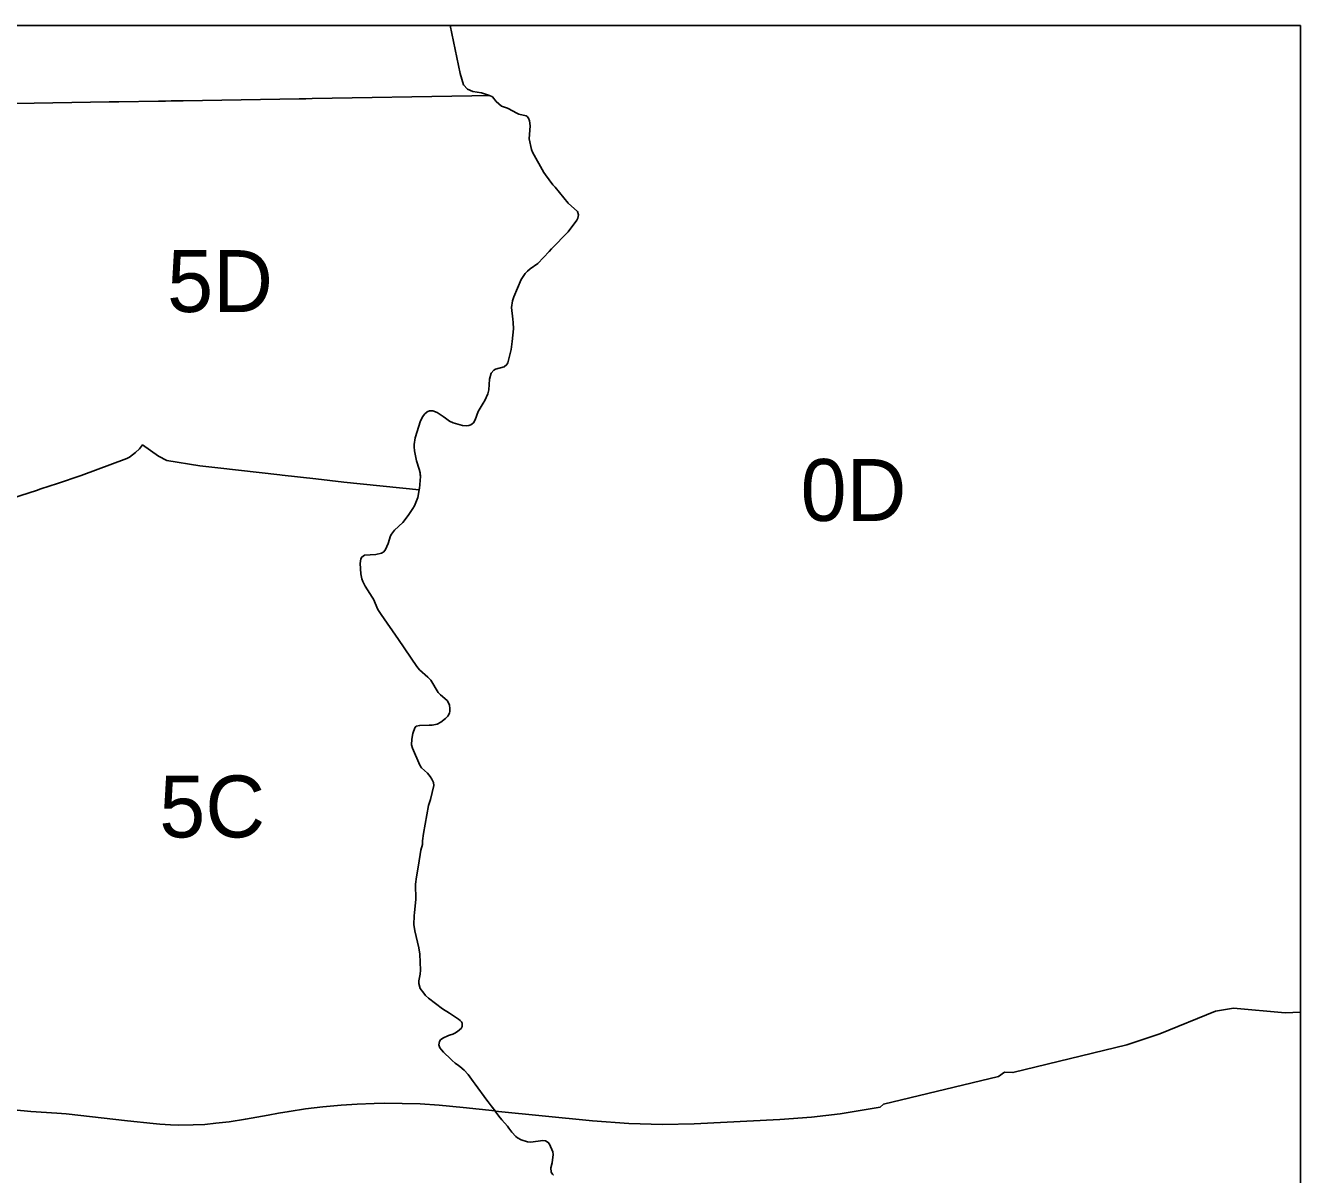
# Model space of a CAD drawing. Extents: x 152750 to 166250, y 378996 to 390000.
# Drawn here: x 162130 to 166250, y 386288 to 390000 of the extents above; entities that cross this region are included whole.
import ezdxf

# ---------------------------------------------------------------- set-up
doc = ezdxf.new("R2010")
doc.units = 0
doc.layers.add('BLT_Nummers', color=7, linetype='Continuous')
doc.layers.add('BLT_Shapes', color=7, linetype='Continuous')

msp = doc.modelspace()

# ---------------------------------------------------------------- linework, layer by layer
at = {"layer": 'BLT_Shapes'}
for p, q in [((163502.8, 390000), (157101, 390000)), ((162560.7, 389755.6), (162432.5, 389753.4)), ((163630.1, 389773.7), (163572.1, 389772.7)), ((163688, 389732.8), (163668.9, 389739.1)), ((163758.8, 389692.2), (163755.7, 389700.3)), ((163760.9, 389675.5), (163758.8, 389692.2)), ((163805.4, 389525.1), (163768.7, 389591.2)), ((163810.2, 389518), (163805.4, 389525.1)), ((163834.3, 389485.3), (163810.2, 389518)), ((163703.9, 389110.2), (163708.2, 389123.6)), ((163699.2, 388953), (163702.2, 388970.4)), ((163702.2, 388970.4), (163703.4, 388978.6)), ((163648.9, 388889.7), (163676.7, 388896.8)), ((163676.7, 388896.8), (163686, 388905)), ((163630, 388857.9), (163634.7, 388876.8)), ((163407.2, 388723.2), (163414.2, 388737.1)), ((163569.1, 388709.5), (163577.5, 388716.4)), ((162959.7, 388547.7), (163068.9, 388535.3)), ((163068.9, 388535.3), (163158.8, 388525.2)), ((163158.8, 388525.2), (163402.6, 388500)), ((163382.4, 388439.1), (163387.6, 388448.2)), ((163313, 388356.8), (163322.6, 388370)), ((163211.8, 388261.6), (163214, 388277.5)), ((163214, 388277.5), (163217.6, 388282.9)), ((163217.6, 388282.9), (163226.2, 388288.7)), ((163213.9, 388228.5), (163211.8, 388261.6)), ((163217.3, 388211.9), (163213.9, 388228.5)), ((163220.4, 388203.3), (163217.3, 388211.9)), ((163227.7, 388189.1), (163220.4, 388203.3)), ((163250.4, 388152.9), (163227.7, 388189.1)), ((163335.1, 388016.5), (163279.1, 388096.7)), ((163394.4, 387928.9), (163335.1, 388016.5)), ((163439.6, 387884.9), (163430.8, 387895.1)), ((163500, 387778.2), (163501.6, 387784.4)), ((163393.1, 387735.9), (163404.2, 387738.7)), ((163404.2, 387738.7), (163434.8, 387739.8)), ((163434.8, 387739.8), (163444, 387739.9)), ((163472.9, 387748.8), (163487.9, 387760.9)), ((163449.1, 387554.8), (163443.5, 387565.7)), ((163416.7, 387389.7), (163432.3, 387479.7)), ((163408.3, 387335.3), (163413.1, 387353.8)), ((163388.2, 387074.9), (163385.4, 387095.5)), ((163401.1, 386913.8), (163405.3, 386934.9)), ((163417.1, 386873.3), (163406.1, 386889.1)), ((163538.7, 386761.1), (163539.3, 386761.9)), ((163534.1, 386637.2), (163529.4, 386640.6)), ((163547.8, 386625.2), (163534.1, 386637.2)), ((162025.7, 386503.7), (162147.9, 386491.8)), ((162981.9, 386491.8), (163035, 386499.8)), ((163256.9, 386517.4), (163289.8, 386518.2)), ((163406.1, 386515.9), (163466.7, 386512)), ((163625.5, 386522.3), (163620.9, 386527.8)), ((163635.4, 386510.3), (163625.5, 386522.3)), ((163647.5, 386493.2), (163635.4, 386510.3)), ((162261.4, 386483.8), (162460.5, 386461.3)), ((163648.2, 386492.3), (163647.5, 386493.2)), ((163659.3, 386476.6), (163648.2, 386492.3)), ((162598.6, 386448.3), (162624.5, 386447.9)), ((163692.3, 386437.9), (163688, 386443.6)), ((163702.1, 386424.9), (163692.3, 386437.9)), ((163714.7, 386411.1), (163702.1, 386424.9)), ((163752.3, 386393.7), (163732.2, 386400.4)), ((163834, 386361.3), (163823.4, 386385.6)), ((163833.1, 386289.3), (163829.1, 386296))]:
    msp.add_line(p, q, dxfattribs=at)
msp.add_lwpolyline([(163502.8, 390000), (163535.2, 389844.9), (163545.6, 389808), (163558.4, 389794.1), (163576.3, 389787), (163604.3, 389782.4), (163630.1, 389773.7), (163638.8, 389769.4), (163651.4, 389754.9), (163668.9, 389739.1), (163688, 389732.8), (163689.6, 389731.7), (163717.5, 389716.4), (163724, 389713.8), (163747.9, 389707.8), (163751.8, 389705.6), (163755.7, 389700.3), (163758.8, 389692.2), (163760.9, 389675.5), (163757.3, 389633.6), (163765.5, 389599), (163768.7, 389591.2), (163805.4, 389525.1), (163810.2, 389518), (163834.3, 389485.3), (163841.5, 389477.3), (163883.6, 389426), (163913.9, 389399.4), (163917.3, 389388.8), (163915, 389378), (163911.5, 389370.7), (163883.5, 389333.4), (163829.9, 389278.5), (163822.6, 389270.4), (163785.9, 389230.9), (163760.8, 389213.4), (163752.4, 389206.6), (163745, 389198.4), (163732.4, 389179), (163708.2, 389123.6), (163703.9, 389110.2), (163701, 389089.4), (163705.4, 389051.7), (163706.6, 389041), (163707, 389019.8), (163703.4, 388978.6), (163702.2, 388970.4), (163699.2, 388953), (163688.7, 388910.6), (163686, 388905), (163676.7, 388896.8), (163648.9, 388889.7), (163643.1, 388886.6), (163634.7, 388876.8), (163630, 388857.9), (163627.2, 388822.8), (163623.8, 388809.6), (163614.1, 388788.1), (163608.8, 388779.8), (163592.5, 388752.8), (163583, 388726.5), (163577.5, 388716.4), (163569.1, 388709.5), (163563.2, 388707.4), (163555.3, 388706.7), (163542.5, 388707.6), (163511.8, 388716.3), (163500, 388722.1), (163487.6, 388731.3), (163480.1, 388736.7), (163460.5, 388750.1), (163446.4, 388755.2), (163436, 388755.5), (163428.7, 388752), (163419.5, 388744.1), (163414.2, 388737.1), (163407.2, 388723.2), (163389.8, 388667.4), (163386.5, 388646.8), (163386.3, 388638.9), (163387.4, 388626.4), (163393.7, 388593.7), (163402.5, 388566.9), (163405.2, 388555), (163406.2, 388542.9), (163403.1, 388503.9), (163402.9, 388502.2), (163402.6, 388500), (163398.3, 388474.8), (163387.6, 388448.2), (163382.4, 388439.1), (163367, 388416.5), (163349.2, 388394.6), (163322.6, 388370), (163313, 388356.8), (163310.1, 388351.5), (163302.5, 388326.8), (163293.8, 388307.3), (163288.2, 388300.1), (163280.9, 388295.5), (163262.9, 388291.2), (163226.2, 388288.7), (163217.6, 388282.9), (163214, 388277.5), (163211.8, 388261.6), (163213.9, 388228.5), (163217.3, 388211.9), (163220.4, 388203.3), (163227.7, 388189.1), (163250.4, 388152.9), (163254.3, 388146.5), (163268.4, 388113.7), (163279.1, 388096.7), (163335.1, 388016.5), (163394.4, 387928.9), (163403.5, 387918.7), (163430.8, 387895.1), (163439.6, 387884.9), (163463.3, 387845.6), (163470.8, 387837.1), (163492.7, 387819.2), (163497.6, 387811.5), (163500, 387804.4), (163502, 387793.6), (163501.6, 387784.4), (163500, 387778.2), (163495.4, 387769), (163487.9, 387760.9), (163472.9, 387748.8), (163461, 387742.9), (163444, 387739.9), (163434.8, 387739.8), (163404.2, 387738.7), (163393.1, 387735.9), (163388.8, 387731.2), (163381.7, 387713.1), (163378.2, 387694.1), (163377.7, 387676), (163380.4, 387665.3), (163404.1, 387610.4), (163409.9, 387601.9), (163429.1, 387584.3), (163437.4, 387573.6), (163443.5, 387565.7), (163449.1, 387554.8), (163450.1, 387545.1), (163438.5, 387500), (163432.3, 387479.7), (163416.7, 387389.7), (163413.1, 387365.7), (163413.1, 387353.8), (163408.3, 387335.3), (163400.1, 387287.6), (163393.6, 387250), (163390.1, 387225.9), (163391.7, 387176), (163387.6, 387134.3), (163386.6, 387124), (163385.4, 387095.5), (163388.2, 387074.9), (163401.6, 387020.8), (163404.5, 387000), (163406.4, 386947.8), (163405.3, 386934.9), (163401.1, 386913.8), (163401.2, 386905.3), (163406.1, 386889.1), (163417.1, 386873.3), (163423.2, 386866.3), (163432.3, 386857.7), (163477.4, 386823.5), (163500, 386808.9), (163529.1, 386790), (163534.9, 386785.9), (163539.1, 386781.7), (163541.4, 386777), (163541.6, 386766.6), (163539.3, 386761.9), (163538.7, 386761.1), (163526.2, 386750), (163517.7, 386744.5), (163510.8, 386741.6), (163500, 386737.6), (163497.6, 386736.7), (163478.9, 386728.2), (163471.5, 386722.6), (163468.2, 386718), (163466, 386707), (163469.5, 386697.3), (163474.9, 386690.6), (163480.6, 386683.4), (163505.2, 386660.2), (163509.4, 386656.2), (163519.1, 386648), (163529.4, 386640.6), (163534.1, 386637.2), (163547.8, 386625.2), (163560.9, 386611.1), (163577, 386588.9), (163583.5, 386579.7), (163620.9, 386527.8), (163625.5, 386522.3), (163635.4, 386510.3), (163648.2, 386492.3), (163962.9, 386460.9), (164080.2, 386453), (164188.8, 386449.7), (164290.9, 386451.9), (164567.7, 386465.9), (164670.2, 386472.8), (164762.6, 386484), (164891.8, 386505.3), (164902.6, 386515), (165274.7, 386604.9), (165293.8, 386618.2), (165320.9, 386617.1), (165689, 386707.4), (165795.4, 386742.4), (165975.1, 386815.3), (166033.6, 386825), (166200.7, 386810.6), (166250, 386812.5), (166250, 390000)], close=True, dxfattribs=at)
for points in [[(163630.1, 389773.7), (163604.3, 389782.4), (163576.3, 389787), (163558.4, 389794.1), (163545.6, 389808), (163535.2, 389844.9), (163502.8, 390000)], [(161394, 389735.8), (161394.2, 389735.8), (161430.1, 389736.4), (161703, 389741.1), (161734.5, 389741.6), (162400.4, 389752.9), (162432.5, 389753.4), (162560.7, 389755.6), (162582.3, 389755.9), (162600.8, 389756.3), (162639.5, 389756.9), (163014.9, 389763.3), (163035.8, 389763.6), (163057.2, 389764), (163572.1, 389772.7), (163630.1, 389773.7)], [(162432.5, 389753.4), (162400.4, 389752.9), (161734.5, 389741.6)], [(162600.8, 389756.3), (162582.3, 389755.9), (162560.7, 389755.6)], [(163572.1, 389772.7), (163057.2, 389764), (163035.8, 389763.6), (163014.9, 389763.3), (162639.5, 389756.9), (162600.8, 389756.3)], [(163668.9, 389739.1), (163651.4, 389754.9), (163638.8, 389769.4), (163630.1, 389773.7)], [(163755.7, 389700.3), (163751.8, 389705.6), (163747.9, 389707.8), (163724, 389713.8), (163717.5, 389716.4), (163689.6, 389731.7), (163688, 389732.8)], [(163768.7, 389591.2), (163765.5, 389599), (163757.3, 389633.6), (163760.9, 389675.5)], [(163913.9, 389399.4), (163883.6, 389426), (163841.5, 389477.3), (163834.3, 389485.3)], [(163745, 389198.4), (163752.4, 389206.6), (163760.8, 389213.4), (163785.9, 389230.9), (163822.6, 389270.4), (163829.9, 389278.5), (163883.5, 389333.4), (163911.5, 389370.7), (163915, 389378), (163917.3, 389388.8), (163913.9, 389399.4)], [(163708.2, 389123.6), (163732.4, 389179), (163745, 389198.4)], [(163703.4, 388978.6), (163707, 389019.8), (163706.6, 389041), (163705.4, 389051.7), (163701, 389089.4), (163703.9, 389110.2)], [(163686, 388905), (163688.7, 388910.6), (163699.2, 388953)], [(163634.7, 388876.8), (163643.1, 388886.6), (163648.9, 388889.7)], [(163592.5, 388752.8), (163608.8, 388779.8), (163614.1, 388788.1), (163623.8, 388809.6), (163627.2, 388822.8), (163630, 388857.9)], [(163386.5, 388646.8), (163389.8, 388667.4), (163407.2, 388723.2)], [(163414.2, 388737.1), (163419.5, 388744.1), (163428.7, 388752)], [(163428.7, 388752), (163436, 388755.5), (163446.4, 388755.2)], [(163446.4, 388755.2), (163460.5, 388750.1), (163480.1, 388736.7), (163487.6, 388731.3), (163500, 388722.1), (163511.8, 388716.3), (163542.5, 388707.6)], [(163577.5, 388716.4), (163583, 388726.5), (163592.5, 388752.8)], [(163542.5, 388707.6), (163555.3, 388706.7), (163563.2, 388707.4), (163569.1, 388709.5)], [(163402.6, 388500), (163158.8, 388525.2), (163068.9, 388535.3), (162959.7, 388547.7), (162952.6, 388548.5), (162751.9, 388570.9), (162693.6, 388577.4), (162586.8, 388594.8), (162559.9, 388608.6), (162508.9, 388645.2), (162498.3, 388632.5), (162485.7, 388620.4), (162466.4, 388605.7), (162458.1, 388601.4), (162310.5, 388546), (162233.8, 388520.7), (162180.4, 388502.8), (162165.8, 388498), (162088.6, 388472.8)], [(162498.3, 388632.5), (162508.9, 388645.2), (162559.9, 388608.6), (162586.8, 388594.8)], [(163387.4, 388626.4), (163386.3, 388638.9), (163386.5, 388646.8)], [(162180.4, 388502.8), (162233.8, 388520.7), (162310.5, 388546), (162458.1, 388601.4), (162466.4, 388605.7)], [(162466.4, 388605.7), (162485.7, 388620.4), (162498.3, 388632.5)], [(163405.2, 388555), (163402.5, 388566.9), (163393.7, 388593.7), (163387.4, 388626.4)], [(162586.8, 388594.8), (162693.6, 388577.4), (162751.9, 388570.9), (162952.6, 388548.5), (162959.7, 388547.7)], [(163402.6, 388500), (163402.9, 388502.2), (163403.1, 388503.9), (163406.2, 388542.9), (163405.8, 388547.2), (163405.2, 388555)], [(162088.6, 388472.8), (162165.8, 388498), (162180.4, 388502.8)], [(163387.6, 388448.2), (163398.3, 388474.8), (163402.6, 388500)], [(163322.6, 388370), (163349.2, 388394.6), (163367, 388416.5), (163382.4, 388439.1)], [(163293.8, 388307.3), (163302.5, 388326.8), (163310.1, 388351.5), (163313, 388356.8)], [(163226.2, 388288.7), (163262.9, 388291.2), (163280.9, 388295.5), (163288.2, 388300.1), (163293.8, 388307.3)], [(163279.1, 388096.7), (163268.4, 388113.7), (163254.3, 388146.5), (163250.4, 388152.9)], [(163430.8, 387895.1), (163403.5, 387918.7), (163394.4, 387928.9)], [(163501.6, 387784.4), (163502, 387793.6), (163500, 387804.4), (163497.6, 387811.5), (163492.7, 387819.2), (163470.8, 387837.1), (163463.3, 387845.6), (163439.6, 387884.9)], [(163487.9, 387760.9), (163495.4, 387769), (163500, 387778.2)], [(163377.7, 387676), (163378.2, 387694.1), (163381.7, 387713.1), (163388.8, 387731.2), (163393.1, 387735.9)], [(163444, 387739.9), (163461, 387742.9), (163472.9, 387748.8)], [(163404.1, 387610.4), (163380.4, 387665.3), (163377.7, 387676)], [(163443.5, 387565.7), (163437.4, 387573.6), (163429.1, 387584.3), (163409.9, 387601.9), (163404.1, 387610.4)], [(163432.3, 387479.7), (163438.5, 387500), (163450.1, 387545.1), (163449.1, 387554.8)], [(163413.1, 387353.8), (163413.1, 387365.7), (163416.7, 387389.7)], [(163390.1, 387225.9), (163393.6, 387250), (163400.1, 387287.6), (163408.3, 387335.3)], [(163385.4, 387095.5), (163386.6, 387124), (163387.6, 387134.3), (163391.7, 387176), (163390.1, 387225.9)], [(163404.5, 387000), (163401.6, 387020.8), (163388.2, 387074.9)], [(163405.3, 386934.9), (163406.4, 386947.8), (163404.5, 387000)], [(163406.1, 386889.1), (163401.2, 386905.3), (163401.1, 386913.8)], [(163432.3, 386857.7), (163423.2, 386866.3), (163417.1, 386873.3)], [(163539.3, 386761.9), (163541.6, 386766.6), (163541.4, 386777), (163539.1, 386781.7), (163534.9, 386785.9), (163529.1, 386790), (163500, 386808.9), (163477.4, 386823.5), (163432.3, 386857.7)], [(166250, 382867.2), (166250, 386812.5), (166200.7, 386810.6), (166033.6, 386825), (165975.1, 386815.3), (165795.4, 386742.4), (165689, 386707.4), (165320.9, 386617.1), (165293.8, 386618.2), (165274.7, 386604.9), (164902.6, 386515), (164891.8, 386505.3), (164762.6, 386484), (164670.2, 386472.8), (164567.7, 386465.9), (164290.9, 386451.9), (164188.8, 386449.7), (164080.2, 386453), (163962.9, 386460.9), (163648.2, 386492.3), (163659.3, 386476.6), (163669.6, 386464.8), (163688, 386443.6), (163692.3, 386437.9), (163702.1, 386424.9), (163714.7, 386411.1), (163720.5, 386406.2), (163732.2, 386400.4), (163752.3, 386393.7), (163763.5, 386392.2), (163801.5, 386397.7), (163810.6, 386396.5), (163819.3, 386391.8), (163823.4, 386385.6), (163834, 386361.3), (163835, 386353.1), (163831.6, 386326), (163827.4, 386309), (163829.1, 386296), (163833.1, 386289.3), (163835.7, 386286.9)], [(163510.8, 386741.6), (163517.7, 386744.5), (163526.2, 386750), (163538.7, 386761.1)], [(163505.2, 386660.2), (163480.6, 386683.4), (163474.9, 386690.6), (163469.5, 386697.3), (163466, 386707), (163468.2, 386718), (163471.5, 386722.6), (163478.9, 386728.2)], [(163478.9, 386728.2), (163497.6, 386736.7), (163500, 386737.6), (163510.8, 386741.6)], [(163529.4, 386640.6), (163519.1, 386648), (163509.4, 386656.2), (163505.2, 386660.2)], [(163620.9, 386527.8), (163583.5, 386579.7), (163577, 386588.9), (163560.9, 386611.1), (163547.8, 386625.2)], [(163647.5, 386493.2), (163544.2, 386504.4), (163466.7, 386512), (163406.1, 386515.9), (163347.3, 386517.8), (163289.8, 386518.2), (163256.9, 386517.4), (163201.6, 386515.1), (163150.5, 386512), (163090.6, 386506.7), (163035, 386499.8), (162981.9, 386491.8), (162948.4, 386486.1), (162914, 386479.2), (162840.8, 386467), (162788.2, 386458.2), (162745.8, 386453.7), (162710, 386449.8), (162671.8, 386448.7), (162624.5, 386447.9), (162598.6, 386448.3), (162564.3, 386451), (162543.3, 386452.5), (162460.5, 386461.3), (162261.4, 386483.8), (162231.7, 386486.1), (162147.9, 386491.8), (162025.7, 386503.7)], [(163035, 386499.8), (163090.6, 386506.7), (163150.5, 386512)], [(163150.5, 386512), (163201.6, 386515.1), (163256.9, 386517.4)], [(163289.8, 386518.2), (163347.3, 386517.8), (163406.1, 386515.9)], [(163466.7, 386512), (163544.2, 386504.4), (163647.5, 386493.2)], [(162147.9, 386491.8), (162231.7, 386486.1), (162261.4, 386483.8)], [(162460.5, 386461.3), (162543.3, 386452.5), (162564.3, 386451), (162598.6, 386448.3)], [(162624.5, 386447.9), (162671.8, 386448.7), (162710, 386449.8), (162745.8, 386453.7), (162788.2, 386458.2), (162840.8, 386467), (162914, 386479.2), (162948.4, 386486.1), (162981.9, 386491.8)], [(163688, 386443.6), (163669.6, 386464.8), (163659.3, 386476.6)], [(163732.2, 386400.4), (163720.5, 386406.2), (163714.7, 386411.1)], [(163810.6, 386396.5), (163801.5, 386397.7), (163763.5, 386392.2), (163752.3, 386393.7)], [(163823.4, 386385.6), (163819.3, 386391.8), (163810.6, 386396.5)], [(163829.1, 386296), (163827.4, 386309), (163831.6, 386326), (163835, 386353.1), (163834, 386361.3)], [(163835.9, 386286.7), (163835.7, 386286.9), (163833.1, 386289.3)]]:
    msp.add_lwpolyline(points, dxfattribs=at)

# ---------------------------------------------------------------- texts
at = {"layer": 'BLT_Nummers'}
for s, p in [('5D', (162588, 389074.4)), ('0D', (164634.8, 388399.4)), ('5C', (162562.6, 387377))]:
    msp.add_text(s, height=200, dxfattribs=at).set_placement(p)

doc.saveas('drawing.dxf')
